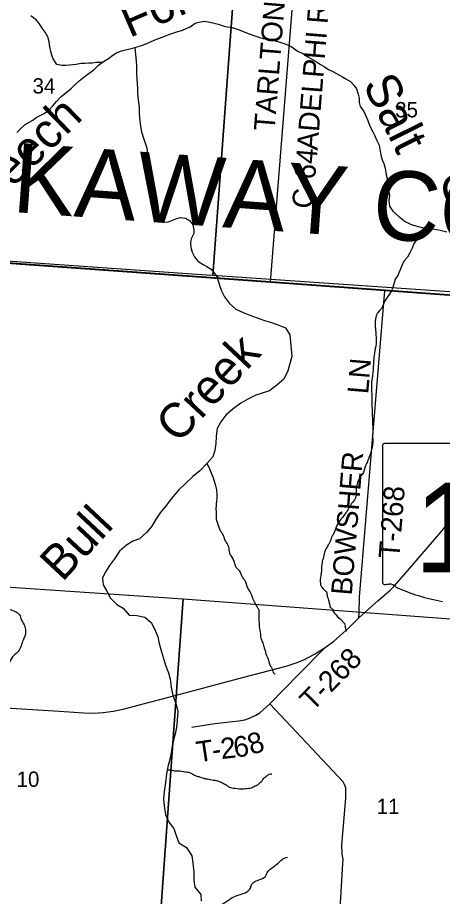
# Model space of a CAD drawing. Extents: x 0 to 42.5, y 0 to 22.
# Drawn here: x 6.921 to 7.502, y 14.815 to 16.014 of the extents above; entities that cross this region are included whole.
import ezdxf

# ---------------------------------------------------------------- set-up
doc = ezdxf.new("R2010")
doc.units = 0
for name, color, linetype in [('GM_X_County_Road', 7, 'Continuous'), ('GM_X_County_Road_Text', 7, 'Continuous'), ('GM_X_County_Text', 7, 'Continuous'), ('GM_X_Interchange_Ramps', 7, 'Continuous'), ('GM_X_Minor_River', 7, 'Continuous'), ('GM_X_Minor_River_Text', 7, 'Continuous'), ('GM_X_Section', 7, 'Continuous'), ('GM_X_Section_Text', 7, 'Continuous'), ('GM_X_State_Route', 7, 'Continuous'), ('GM_X_State_Shield', 7, 'Continuous'), ('GM_X_Township', 7, 'Continuous'), ('GM_X_Township_Road', 7, 'Continuous'), ('GM_X_Township_Road_Text', 7, 'Continuous'), ('SH_Cut_Line', 7, 'Continuous')]:
    doc.layers.add(name, color=color, linetype=linetype)

msp = doc.modelspace()

# ---------------------------------------------------------------- linework, layer by layer
at = {"layer": 'GM_X_County_Road'}
for p, q in [((7.2668, 15.653), (7.3065, 16.1521)), ((6.3385, 15.72), (7.2668, 15.653)), ((7.2668, 15.653), (7.4228, 15.6417)), ((7.4228, 15.6417), (7.8769, 15.6085))]:
    msp.add_line(p, q, dxfattribs=at)
at = {"layer": 'GM_X_Interchange_Ramps'}
msp.add_lwpolyline([(5.0849, 14.1), (8.0699, 14.1), (8.0701, 14.1026), (8.0729, 14.128), (8.0955, 14.4869), (8.1568, 15.4132), (8.1688, 15.5951), (8.1699, 15.6154), (8.0481, 15.6267), (7.9796, 15.6342), (7.9533, 15.6361), (7.9192, 15.6368), (7.9181, 15.6067), (7.8815, 15.6084), (7.8767, 15.6088), (7.4227, 15.6419), (7.2667, 15.6533), (5.9292, 15.7498)], dxfattribs=at)
at = {"layer": 'GM_X_Minor_River'}
for points in [[(7.0366, 15.9529), (7.0284, 15.9528), (7.0229, 15.952), (7.0182, 15.9517), (7.0131, 15.9515), (7.0078, 15.9514), (7.0011, 15.9501), (6.992, 15.9492), (6.9869, 15.9488), (6.9814, 15.9486), (6.9744, 15.95), (6.9697, 15.9578), (6.9676, 15.9626), (6.9663, 15.9675), (6.965, 15.9742), (6.964, 15.981), (6.9622, 15.9878), (6.9588, 15.9939), (6.9546, 15.9996), (6.9508, 16.0054), (6.9463, 16.0107), (6.9389, 16.0162)], [(6.9201, 15.8573), (6.9249, 15.862), (6.9315, 15.868), (6.9416, 15.8742), (6.9465, 15.8778), (6.9517, 15.8805), (6.9574, 15.8831), (6.9638, 15.8876), (6.9693, 15.8935), (6.9743, 15.8995), (6.9805, 15.9061), (6.9891, 15.9133), (6.9948, 15.9178), (6.9999, 15.9233), (7.0049, 15.9275), (7.0098, 15.9314), (7.0186, 15.938), (7.025, 15.9429), (7.0313, 15.949), (7.0383, 15.9541), (7.045, 15.958), (7.051, 15.9629), (7.056, 15.9657), (7.0615, 15.968), (7.0666, 15.9693), (7.0727, 15.971), (7.078, 15.9723), (7.0844, 15.9741), (7.0905, 15.976), (7.0968, 15.9783), (7.1036, 15.9813), (7.1097, 15.9839), (7.1186, 15.9871), (7.1243, 15.9895), (7.129, 15.9912), (7.1387, 15.9944), (7.1465, 15.9968), (7.1514, 15.9989), (7.1569, 16.0013), (7.1638, 16.0062), (7.171, 16.0084), (7.1763, 16.009), (7.1837, 16.0078), (7.1896, 16.0065), (7.1951, 16.0051), (7.2047, 16.002), (7.2142, 16.0003), (7.2212, 15.998), (7.226, 15.9962), (7.2362, 15.9924), (7.2453, 15.9891), (7.2506, 15.9872), (7.2565, 15.9853), (7.2622, 15.9845), (7.2671, 15.9831), (7.2735, 15.9821), (7.2807, 15.9802), (7.2868, 15.9781), (7.2949, 15.9746), (7.3046, 15.9679), (7.3103, 15.9656), (7.3165, 15.961), (7.3218, 15.9582), (7.3281, 15.9543), (7.3349, 15.9499), (7.34, 15.9471), (7.3459, 15.9431), (7.3508, 15.9409), (7.3569, 15.9377), (7.365, 15.9329), (7.3697, 15.9304), (7.3758, 15.9266), (7.3807, 15.9216)], [(7.0814, 15.9733), (7.0829, 15.954), (7.0834, 15.948), (7.0836, 15.9428), (7.0836, 15.9368), (7.084, 15.9303), (7.0845, 15.9237), (7.0849, 15.9178), (7.0849, 15.9119), (7.0852, 15.9047), (7.086, 15.8984), (7.0869, 15.8906), (7.0873, 15.8832), (7.0876, 15.8783), (7.088, 15.8722), (7.0887, 15.8663), (7.0899, 15.8597), (7.0923, 15.8521), (7.0944, 15.8452), (7.0963, 15.8405), (7.0978, 15.8357), (7.0985, 15.8289), (7.0989, 15.8237), (7.0998, 15.8177), (7.1013, 15.8101), (7.1017, 15.8051), (7.1013, 15.7985), (7.1015, 15.7913), (7.1045, 15.7848), (7.1069, 15.7797), (7.1099, 15.7734), (7.1101, 15.7685), (7.1099, 15.7637), (7.1101, 15.7582), (7.1107, 15.7535), (7.1114, 15.7478), (7.1137, 15.7423), (7.1163, 15.7373), (7.1214, 15.7348), (7.1269, 15.7352), (7.1319, 15.7372), (7.1385, 15.7397), (7.1438, 15.7412), (7.151, 15.7402), (7.1563, 15.7367), (7.1605, 15.731), (7.1616, 15.7242), (7.1616, 15.7191), (7.1583, 15.712), (7.1572, 15.7067), (7.1579, 15.7001), (7.1596, 15.694), (7.1625, 15.6875), (7.1674, 15.6814), (7.1746, 15.6769), (7.1797, 15.6744), (7.1856, 15.6705), (7.1944, 15.6586)], [(7.3807, 15.9216), (7.3839, 15.9167), (7.3864, 15.9096), (7.3877, 15.9041), (7.3877, 15.8981), (7.3892, 15.8925), (7.3937, 15.8865), (7.3966, 15.8809), (7.3996, 15.8737), (7.4024, 15.8659), (7.4064, 15.8581), (7.409, 15.8524), (7.4115, 15.8473), (7.4149, 15.8399), (7.4158, 15.8342), (7.4175, 15.8264), (7.4192, 15.8197), (7.4214, 15.8148), (7.4231, 15.8087), (7.4246, 15.7996), (7.4259, 15.7944), (7.4267, 15.7897), (7.4276, 15.783), (7.4284, 15.7764), (7.4293, 15.7711), (7.4285, 15.7642), (7.4294, 15.7568), (7.4336, 15.75), (7.4414, 15.7429), (7.4506, 15.7357), (7.459, 15.7314), (7.4639, 15.7301), (7.4686, 15.7287), (7.4743, 15.7276), (7.4815, 15.7264), (7.4884, 15.7256), (7.4984, 15.7237), (7.5077, 15.7217)], [(7.4784, 15.7269), (7.477, 15.7243), (7.4732, 15.7189), (7.4675, 15.712), (7.4625, 15.7056), (7.4602, 15.6992), (7.4566, 15.692), (7.4537, 15.6869), (7.4486, 15.6816), (7.4457, 15.6744), (7.4408, 15.6621), (7.4368, 15.6572), (7.4345, 15.649), (7.4326, 15.6426)], [(7.1939, 15.6586), (7.1992, 15.6419), (7.2036, 15.6327), (7.2107, 15.624), (7.2194, 15.6159), (7.2292, 15.6113), (7.2382, 15.6078), (7.2586, 15.6008), (7.2681, 15.5977), (7.2779, 15.5942), (7.2873, 15.5907), (7.2929, 15.5812), (7.295, 15.5614), (7.2957, 15.5516), (7.2902, 15.5319), (7.2849, 15.5205), (7.2753, 15.5123), (7.2654, 15.5048), (7.2552, 15.5014), (7.2464, 15.4989), (7.2358, 15.4932), (7.2259, 15.4876), (7.2156, 15.4801), (7.2057, 15.4715), (7.1985, 15.4625), (7.1935, 15.453), (7.1922, 15.4428), (7.1918, 15.4329), (7.1906, 15.4231), (7.1878, 15.4144), (7.1798, 15.4053), (7.1699, 15.3952), (7.1604, 15.3877), (7.1505, 15.3779), (7.1409, 15.3688), (7.131, 15.3572), (7.1245, 15.3485), (7.1157, 15.3379), (7.1092, 15.3285), (7.1046, 15.3198), (7.0973, 15.3112), (7.0874, 15.3025), (7.0786, 15.2992), (7.0699, 15.2939), (7.0604, 15.286), (7.0535, 15.2755), (7.0466, 15.2664), (7.0412, 15.2574), (7.037, 15.2487), (7.0377, 15.24), (7.0429, 15.2312), (7.0481, 15.2217), (7.0568, 15.2132), (7.0654, 15.2079), (7.0733, 15.1983), (7.0839, 15.1982), (7.0948, 15.1955), (7.1035, 15.1882), (7.1087, 15.1787), (7.1128, 15.1688), (7.1146, 15.1597), (7.1175, 15.1482), (7.1205, 15.1395), (7.1234, 15.1288), (7.1272, 15.1197), (7.1294, 15.111), (7.1308, 15.1003), (7.133, 15.0886), (7.1374, 15.0783), (7.14, 15.0669), (7.1387, 15.0494), (7.1371, 15.0403), (7.1348, 15.0316), (7.132, 15.0199), (7.1308, 15.0104), (7.1288, 15.0013), (7.1265, 14.9915), (7.1245, 14.982), (7.1229, 14.9699), (7.1213, 14.9574), (7.1205, 14.9479), (7.1211, 14.938), (7.1229, 14.9263), (7.1278, 14.916), (7.1345, 14.9072), (7.1378, 14.8977), (7.1412, 14.8878), (7.1517, 14.8813), (7.1592, 14.8702), (7.1606, 14.86), (7.1617, 14.8478), (7.162, 14.8364), (7.1634, 14.8273), (7.1713, 14.817), (7.1719, 14.8083)]]:
    msp.add_lwpolyline(points, dxfattribs=at)
for points in [[(7.4322, 15.6408), (7.421, 15.623), (7.4191, 15.6188), (7.4171, 15.6156), (7.412, 15.6095), (7.4103, 15.6031), (7.4097, 15.5999), (7.4095, 15.5978), (7.41, 15.5898), (7.4103, 15.587), (7.4108, 15.5781), (7.411, 15.5741), (7.41, 15.5636), (7.409, 15.5589), (7.4076, 15.5466), (7.4072, 15.5413), (7.4061, 15.5258), (7.4052, 15.5196), (7.4048, 15.5026), (7.405, 15.4961), (7.4054, 15.4801), (7.4056, 15.4744), (7.4061, 15.46), (7.4064, 15.4549), (7.4061, 15.4428), (7.4063, 15.4379), (7.4047, 15.4241), (7.4031, 15.4188), (7.3985, 15.4066), (7.3966, 15.4023), (7.392, 15.3906), (7.3889, 15.3865), (7.3849, 15.3769), (7.3839, 15.3734), (7.3833, 15.3596), (7.3785, 15.3523), (7.3703, 15.3391), (7.3669, 15.3345), (7.3591, 15.3238), (7.3564, 15.3184), (7.3525, 15.309), (7.3506, 15.3058), (7.3476, 15.2981), (7.3456, 15.2943), (7.3428, 15.2894), (7.3407, 15.2855), (7.3401, 15.2823), (7.3378, 15.2734), (7.337, 15.2706), (7.3361, 15.2582), (7.3352, 15.2527), (7.3347, 15.2417), (7.3371, 15.236), (7.3416, 15.2316), (7.3429, 15.2301), (7.3442, 15.224), (7.345, 15.2219), (7.3466, 15.2162), (7.3473, 15.2136), (7.3492, 15.2084), (7.3509, 15.2071), (7.3514, 15.2058), (7.3544, 15.2006), (7.3563, 15.1987), (7.3606, 15.1941), (7.3629, 15.1925), (7.3659, 15.1887), (7.3675, 15.187), (7.3685, 15.1832), (7.369, 15.1807), (7.3705, 15.1766)], [(7.1798, 15.4053), (7.1932, 15.357), (7.192, 15.3441), (7.1923, 15.3388), (7.1932, 15.3262), (7.1948, 15.3222), (7.1984, 15.3129), (7.2008, 15.3094), (7.2043, 15.3009), (7.2062, 15.2978), (7.2095, 15.2894), (7.2101, 15.2849), (7.2115, 15.2809), (7.2166, 15.2723), (7.2173, 15.2695), (7.2212, 15.2619), (7.2237, 15.2592), (7.2279, 15.2506), (7.2309, 15.2468), (7.2354, 15.235), (7.2386, 15.2302), (7.2432, 15.219), (7.2454, 15.2152), (7.249, 15.2085), (7.2501, 15.2066), (7.2508, 15.2017), (7.2507, 15.1921), (7.2509, 15.1883), (7.252, 15.1773), (7.2527, 15.1735), (7.2541, 15.1648), (7.2554, 15.1621), (7.2575, 15.1555), (7.2586, 15.1524), (7.2612, 15.1433), (7.263, 15.1397), (7.2662, 15.1296), (7.2684, 15.126), (7.2716, 15.119), (7.2731, 15.1182)], [(6.5987, 15.368), (6.6079, 15.3657), (6.6143, 15.3639), (6.6164, 15.3629), (6.6311, 15.3618), (6.6343, 15.3612), (6.6611, 15.361), (6.6645, 15.3615), (6.6923, 15.3611), (6.6955, 15.3601), (6.7194, 15.3567), (6.7222, 15.3554), (6.7443, 15.3533), (6.7469, 15.3526), (6.765, 15.3493), (6.7671, 15.3479), (6.7805, 15.3443), (6.7818, 15.343), (6.7914, 15.3377), (6.7927, 15.3356), (6.8043, 15.3285), (6.8058, 15.3254), (6.816, 15.3158), (6.8201, 15.3071), (6.8213, 15.3029), (6.8228, 15.2987), (6.8254, 15.2942), (6.8286, 15.2837), (6.8291, 15.2794), (6.8341, 15.2668), (6.8348, 15.2623), (6.8389, 15.251), (6.8427, 15.2472), (6.8473, 15.2392), (6.8499, 15.236), (6.8559, 15.2291), (6.8595, 15.2267), (6.8666, 15.2215), (6.8714, 15.22), (6.8793, 15.2183), (6.8836, 15.2175), (6.8887, 15.2161), (6.8915, 15.2159), (6.8968, 15.2149), (6.8998, 15.2137), (6.9066, 15.2081), (6.9122, 15.2056), (6.9244, 15.1975), (6.9255, 15.194), (6.9298, 15.1851), (6.9313, 15.1813), (6.9308, 15.1696), (6.9285, 15.1645), (6.922, 15.1491), (6.9158, 15.1435), (6.9045, 15.1259), (6.8956, 15.1194), (6.8899, 15.1127), (6.8779, 15.1038), (6.8758, 15.0989), (6.8747, 15.0968), (6.8729, 15.0901), (6.8719, 15.0872), (6.8706, 15.0786), (6.8698, 15.0767), (6.8698, 15.0754), (6.8694, 15.0701), (6.8674, 15.0635), (6.867, 15.0574), (6.8641, 15.0414), (6.8618, 15.0356), (6.8572, 15.0247), (6.8536, 15.0213), (6.8456, 15.0143), (6.838, 15.0102), (6.8236, 14.9993), (6.8154, 14.9963), (6.805, 14.9927), (6.7994, 14.9911), (6.7922, 14.9889), (6.7876, 14.9873), (6.774, 14.9818), (6.7723, 14.9792), (6.7615, 14.9716), (6.7569, 14.9696), (6.7549, 14.969), (6.7525, 14.9607)], [(7.1256, 14.987), (7.1327, 14.9867), (7.134, 14.9863), (7.14, 14.9861), (7.15, 14.9848), (7.1559, 14.9837), (7.1638, 14.9797), (7.1685, 14.9781), (7.176, 14.9757), (7.1805, 14.9749), (7.1883, 14.9733), (7.193, 14.9728), (7.1996, 14.9701), (7.2022, 14.9689), (7.2058, 14.9668), (7.2078, 14.9654), (7.212, 14.9631), (7.2154, 14.9625), (7.2265, 14.9614), (7.2282, 14.9614), (7.2363, 14.9622), (7.2405, 14.9629), (7.2454, 14.9653), (7.2481, 14.9662), (7.2518, 14.9695), (7.2541, 14.9712), (7.2583, 14.9768), (7.2612, 14.9788), (7.2648, 14.9814), (7.2685, 14.9818)], [(7.1696, 14.7954), (7.1676, 14.7945), (7.1712, 14.7935), (7.1802, 14.7938), (7.191, 14.7982), (7.1963, 14.8021), (7.2014, 14.8046), (7.2124, 14.8118), (7.2208, 14.8157), (7.2395, 14.8266), (7.2413, 14.8315), (7.2468, 14.8357), (7.2606, 14.8435), (7.2619, 14.8467), (7.2705, 14.8551), (7.2752, 14.8584), (7.2825, 14.8651), (7.2866, 14.8673), (7.2898, 14.868)]]:
    msp.add_spline(points, degree=3, dxfattribs=at)
at = {"layer": 'GM_X_Section'}
for points in [[(6.7311, 16.1941), (7.2242, 16.1562), (7.1878, 15.6618), (7.1793, 15.6623), (6.6857, 15.6968)], [(7.2242, 16.1562), (7.7207, 16.1288), (7.6812, 15.628), (7.6698, 15.6288), (7.1878, 15.6618)], [(6.6483, 15.2542), (7.1473, 15.2209), (7.1103, 14.706), (6.6121, 14.7442)], [(7.1473, 15.2209), (7.6404, 15.1841), (7.6095, 14.6675), (7.1103, 14.706)]]:
    msp.add_lwpolyline(points, close=True, dxfattribs=at)
at = {"layer": 'GM_X_State_Route'}
for points in [[(7.3872, 15.1948), (7.4135, 15.218), (7.4298, 15.2321), (7.4358, 15.238), (7.4514, 15.256), (7.4995, 15.3119), (7.5219, 15.3396)], [(7.3414, 15.1542), (7.353, 15.1629), (7.3732, 15.1805), (7.3872, 15.1948)], [(6.8827, 15.0734), (6.9779, 15.0672), (7.0116, 15.0651), (7.0252, 15.0645), (7.0379, 15.0654), (7.0518, 15.0672), (7.0671, 15.0704), (7.0925, 15.0772), (7.1277, 15.0867), (7.1942, 15.1041), (7.2406, 15.1165), (7.288, 15.1288), (7.3017, 15.1335), (7.312, 15.1376), (7.3269, 15.1453), (7.3414, 15.1542)]]:
    msp.add_lwpolyline(points, dxfattribs=at)
at = {"layer": 'GM_X_State_Shield'}
for p, q in [((7.4196, 15.4294), (7.4196, 15.2437)), ((7.5122, 15.4325), (7.4227, 15.4325))]:
    msp.add_line(p, q, dxfattribs=at)
for centre, major_axis, start_param, end_param in [((7.4231, 15.4298), (0.00354, 0), 1.712693, 3.28349), ((7.4232, 15.2433), (0.00357, 0), 3.00124, 4.508301), ((7.4237, 15.2623), (0.0273, 0), 4.665946, 4.897461), ((7.4293, 15.233), (0.00984, 0), 0.519207, 1.627899), ((7.5535, 15.3998), (0.2342, 0), 4.195997, 4.488961)]:
    msp.add_ellipse(centre, major_axis=major_axis, ratio=0.8, start_param=start_param, end_param=end_param, dxfattribs=at)
at = {"layer": 'GM_X_Township'}
msp.add_lwpolyline([(8.2478, 16.5901), (8.1793, 15.7911), (8.1778, 15.7616), (8.1756, 15.7214), (8.1727, 15.6669), (8.1708, 15.6304), (8.1699, 15.6154), (8.0481, 15.6267), (7.9796, 15.6342), (7.9533, 15.6361), (7.9192, 15.6368), (7.9181, 15.6067), (7.8815, 15.6084), (7.8767, 15.6088), (7.4227, 15.6419), (7.2667, 15.6533), (5.9292, 15.7498), (5.2142, 15.7986), (5.2389, 16.1139)], dxfattribs=at)
at = {"layer": 'GM_X_Township_Road'}
for p, q in [((7.3054, 15.1178), (7.3414, 15.1542)), ((7.2655, 15.0773), (7.3054, 15.1178))]:
    msp.add_line(p, q, dxfattribs=at)
for points in [[(7.3872, 15.1948), (7.3877, 15.2017), (7.3884, 15.2229), (7.4228, 15.6417)], [(7.3414, 15.1542), (7.353, 15.1629), (7.3732, 15.1805), (7.3872, 15.1948)], [(7.159, 15.0457), (7.1903, 15.0508), (7.2105, 15.053), (7.2232, 15.0541), (7.2314, 15.0555), (7.2377, 15.0577), (7.2467, 15.0618), (7.2518, 15.0651), (7.2655, 15.0773)], [(7.413, 14.1), (7.4059, 14.1125), (7.4007, 14.1203), (7.3987, 14.1238), (7.3912, 14.1455), (7.3844, 14.1663), (7.3757, 14.2166), (7.3622, 14.2862), (7.345, 14.3706), (7.3396, 14.3953), (7.3345, 14.4223), (7.3333, 14.43), (7.3336, 14.4366), (7.3484, 14.5915), (7.3572, 14.7205), (7.3656, 14.8595), (7.3657, 14.8654), (7.3647, 14.8724), (7.3643, 14.8846), (7.3695, 14.9488), (7.3694, 14.9629), (7.3679, 14.9675), (7.3659, 14.9711), (7.2655, 15.0773)]]:
    msp.add_lwpolyline(points, dxfattribs=at)
at = {"layer": 'SH_Cut_Line'}
for points in [[(3.7213, 15.9037), (4.4437, 15.8535), (4.576, 15.8439), (4.7033, 15.8346), (4.834, 15.8246), (5.0466, 15.8101), (5.2142, 15.7986), (5.9292, 15.7498), (7.2667, 15.6533), (7.4227, 15.6419), (7.8767, 15.6088), (7.8815, 15.6084), (7.9181, 15.6067), (7.9192, 15.6368), (7.9533, 15.6361), (7.9796, 15.6342), (8.0481, 15.6267), (8.1699, 15.6154), (8.1708, 15.6304), (8.1727, 15.6669), (8.1756, 15.7214), (8.1778, 15.7616), (8.1793, 15.7911), (8.2478, 16.5901)], [(2.1, 14.1), (8.0699, 14.1), (8.0701, 14.1026), (8.0729, 14.128), (8.0955, 14.4869), (8.1568, 15.4132), (8.1688, 15.5951), (8.1699, 15.6154), (8.0481, 15.6267), (7.9796, 15.6342), (7.9533, 15.6361), (7.9192, 15.6368), (7.9181, 15.6067), (7.8815, 15.6084), (7.8767, 15.6088), (7.4227, 15.6419), (7.2667, 15.6533), (5.9292, 15.7498)]]:
    msp.add_lwpolyline(points, dxfattribs=at)

# ---------------------------------------------------------------- texts
at = {"layer": 'GM_X_County_Road_Text'}
for s, rotation, p in [('ADELPHI RD', 85.4588, (7.3308, 15.8322)), ('TARLTON', 85.4316, (7.2721, 15.8586)), ('C-64', 85.1793, (7.3241, 15.7524))]:
    msp.add_text(s, height=0.02841, rotation=rotation, dxfattribs=at).set_placement(p)
at = {"layer": 'GM_X_County_Text'}
msp.add_text('PICKAWAY COUNTY', height=0.094697, rotation=355.8529, dxfattribs=at).set_placement((6.702, 15.7641))
at = {"layer": 'GM_X_Minor_River_Text'}
for s, rotation, p in [('Fork', 23.3764, (7.0738, 15.9859)), ('Salt', 296.3741, (7.3922, 15.9228)), ('Beech', 44.377, (6.8836, 15.7512)), ('Creek', 23.3765, (7.5117, 15.7458)), ('Creek', 47.0008, (7.1404, 15.4311)), ('Bull', 47.0007, (6.982, 15.2426))]:
    msp.add_text(s, height=0.04735, rotation=rotation, dxfattribs=at).set_placement(p)
at = {"layer": 'GM_X_Section_Text'}
for s, p in [('34', (6.9414, 15.9103)), ('35', (7.437, 15.8778)), ('10', (6.9196, 14.9641)), ('11', (7.4117, 14.927))]:
    msp.add_text(s, height=0.02093, rotation=0, dxfattribs=at).set_placement(p)
at = {"layer": 'GM_X_State_Shield'}
msp.add_text('180', height=0.12233, dxfattribs=at).set_placement((7.4632, 15.2568))
at = {"layer": 'GM_X_Township_Road_Text'}
for s, height, rotation, p in [('LN', 0.02841, 85.321, (7.4001, 15.4995)), ('BOWSHER', 0.02841, 85.3535, (7.3776, 15.2249)), ('T-268', 0.02841, 85.5135, (7.4425, 15.2748)), ('T-268', 0.02841, 45.3969, (7.3239, 15.0661)), ('T', 0.0284, 8.4477, (7.1673, 14.9974)), ('2', 0.0284, 6.0689, (7.1996, 15.002)), ('6', 0.0284, 7.3249, (7.2177, 15.0039)), ('8', 0.0284, 17.7584, (7.2405, 15.0074)), ('-', 0.0284, 7.5781, (7.1882, 15.0005))]:
    msp.add_text(s, height=height, rotation=rotation, dxfattribs=at).set_placement(p)

doc.saveas('drawing.dxf')
